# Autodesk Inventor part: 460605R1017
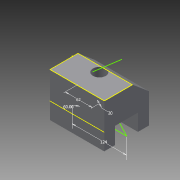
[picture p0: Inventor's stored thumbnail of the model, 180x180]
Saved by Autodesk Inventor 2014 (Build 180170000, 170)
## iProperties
Created: 2016-06
Part Number: 460605R1017
Material: 일반
Document SubType Name: Modeling
Designer: 601-
Density: 1 g/cm^3
Appearance: 기본값
Author: 601-
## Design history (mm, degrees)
sketch "스케치1"
  geometry: L1 (0, 0)-(-26, 0); L2 (0, 0)-(26, 0); L3 (-26, 0)-(-26, -38); L4 (-26, -38)-(-51, -38); L5 (-51, -38)-(-51, 62); L6 (26, 0)-(26, -38); L7 (26, -38)-(51, -38); L8 (51, -38)-(51, 30); L9 (-51, 62)-(12.864, 62); L10 (51, 30)-(12.864, 62)
  constraints: 20 end point, 6 perpendicular, 1 collinear, 1 horizontal
  dimensions: "d0" = 26 distance of L1.start L1.end; "d1" = 26 distance of L1.start L2.end; "d2" = 38 distance of L1.end L3.end; "d3" = 25 distance of L3.end L4.end; "d4" = 100 distance of L4.end L5.end; "d6" = 38 distance of L2.end L6.end; "d7" = 25 distance of L6.end L7.end; "d10" = 50 deg angle of L8 L10; "d11" = 68 distance of L7.end L8.end
extrude "돌출1" new body sketch "스케치1" distance "d12" = 124; taper "d13" = 0 deg
sketch "스케치2"
  geometry: L1 (0, 50.619)-(58.302, -50.363); L2 (58.302, -50.363)-(0, 50.619); L3 (0, -51)-(124, -51) reference; 1 further point
  constraints: 4 end point, 1 collinear
  dimensions: "d14" = 60 deg angle of L3 L2
sketch "스케치3"
  geometry: L1 (0, -33.11)-(-124, -33.11); L2 (-124, -33.11)-(-93.792, 0); L3 (42.749, -22.518)-(-112.81, 112.979); 1 further point
  constraints: 6 end point, 1 horizontal
  dimensions: "d15" = 124 distance of L1.start L1.end
sketch "스케치4"
  geometry: L1 (0, 12.864)-(0, 51) reference; C1 r 10 at (62, 0); 2 further points
  constraints: 1 centre point, 1 coincident
  dimensions: "d16" = 62 distance from line of point (62, 0) L1; "d17" = 20 diameter of C1
sketch "스케치5"
  geometry: L1 (0, 0)-(0, 63.864) reference; C1 r 14.716 at (62, 51); 2 further points
  constraints: 1 centre point, 1 coincident
  dimensions: "d18" = 62 distance from line of point (62, 51) L1
sketch "스케치6"
  geometry: L1 (0, 0)-(0, 63.864) reference; L2 (0, 0)-(124, 0) reference; L3 (124, 63.864)-(124, 0) reference; L4 (0, 63.864)-(124, 63.864) reference; 1 further point
extrude "돌출2" cut sketch "스케치5" distance "d19" = 124; taper "d20" = 0 deg
node "솔리드1"
